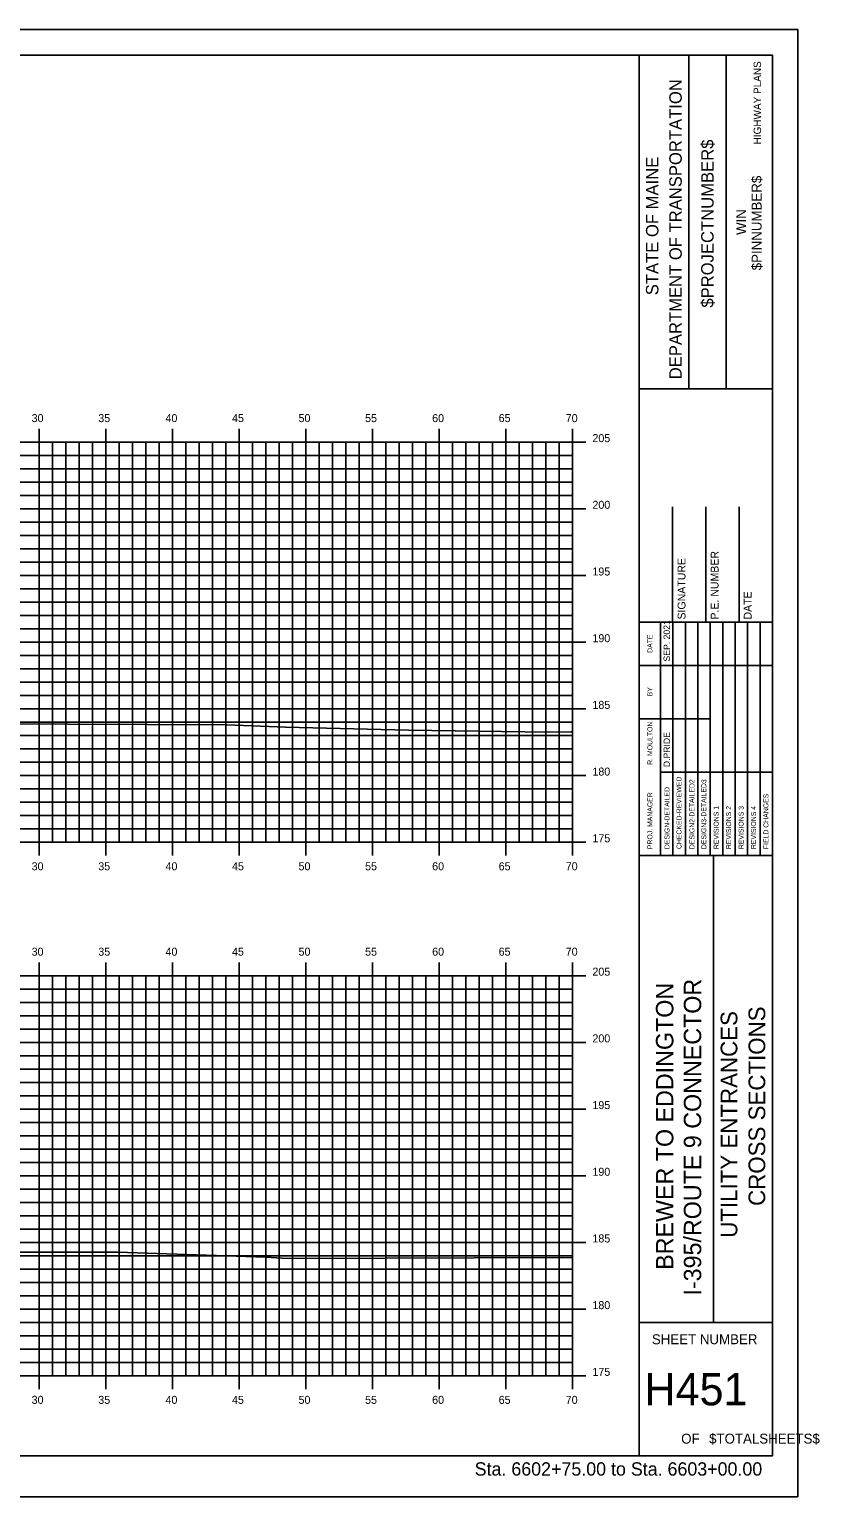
# Model space of a CAD drawing. Extents: x 1724405 to 1724577, y 459560 to 459670.
# Drawn here: x 1724517.3 to 1724576.5, y 459559.6 to 459669.6 of the extents above; entities that cross this region are included whole.
import ezdxf

# ---------------------------------------------------------------- set-up
doc = ezdxf.new("R2010")
doc.units = 0
for name, color, linetype in [('BORDER', 7, 'Continuous'), ('H_V ANNOTATION', 7, 'Continuous'), ('HIGHWAY_TITLE', 7, 'Continuous'), ('MAJOR', 7, 'Continuous'), ('MINOR', 7, 'Continuous'), ('PLOT BOUNDARY', 7, 'Continuous'), ('S_Roadway_Centerline', 7, 'Continuous')]:
    doc.layers.add(name, color=color, linetype=linetype)

msp = doc.modelspace()

# ---------------------------------------------------------------- linework, layer by layer
at = {"layer": 'BORDER'}
for p, q in [((1724562.99, 459562.61), (1724562.99, 459667.61)), ((1724566.71, 459642.61), (1724566.71, 459667.61)), ((1724569.51, 459642.61), (1724569.51, 459667.61)), ((1724562.99, 459642.61), (1724572.99, 459642.61)), ((1724565.49, 459625.12), (1724565.49, 459633.76)), ((1724567.99, 459625.12), (1724567.99, 459633.76)), ((1724570.49, 459625.12), (1724570.49, 459633.76)), ((1724562.99, 459625.12), (1724572.99, 459625.12)), ((1724562.99, 459607.62), (1724572.99, 459607.62)), ((1724568.58, 459572.62), (1724568.58, 459607.62)), ((1724562.99, 459572.62), (1724572.99, 459572.62))]:
    msp.add_line(p, q, dxfattribs=at)
msp.add_lwpolyline([(1724412.99, 459562.61), (1724572.99, 459562.61), (1724572.99, 459667.61), (1724412.99, 459667.61)], close=True, dxfattribs=at)
for points in [[(1724564.6, 459621.87), (1724564.6, 459625.12)], [(1724565.53, 459607.62), (1724565.53, 459625.12)], [(1724566.47, 459625.12), (1724566.47, 459607.62)], [(1724567.4, 459607.62), (1724567.4, 459625.12)], [(1724568.33, 459607.62), (1724568.33, 459625.12)], [(1724569.26, 459607.62), (1724569.26, 459625.12)], [(1724570.19, 459607.62), (1724570.19, 459625.12)], [(1724571.12, 459607.62), (1724571.12, 459625.12)], [(1724572.06, 459607.62), (1724572.06, 459625.12)], [(1724564.6, 459607.62), (1724564.6, 459624.41)], [(1724562.99, 459621.87), (1724572.99, 459621.87)], [(1724562.99, 459617.87), (1724564.6, 459617.87)], [(1724564.6, 459617.87), (1724568.33, 459617.87)], [(1724564.6, 459613.87), (1724572.99, 459613.87)]]:
    msp.add_lwpolyline(points, dxfattribs=at)
at = {"layer": 'MAJOR'}
for p, q in [((1724517.99, 459639.61), (1724517.99, 459638.61)), ((1724522.99, 459639.61), (1724522.99, 459638.61)), ((1724527.99, 459639.61), (1724527.99, 459638.61)), ((1724532.99, 459639.61), (1724532.99, 459638.61)), ((1724537.99, 459639.61), (1724537.99, 459638.61)), ((1724542.99, 459639.61), (1724542.99, 459638.61)), ((1724547.99, 459639.61), (1724547.99, 459638.61)), ((1724552.99, 459639.61), (1724552.99, 459638.61)), ((1724557.99, 459639.61), (1724557.99, 459638.61)), ((1724417.99, 459638.61), (1724557.99, 459638.61)), ((1724417.99, 459638.61), (1724557.99, 459638.61)), ((1724517.99, 459608.61), (1724517.99, 459638.61)), ((1724522.99, 459608.61), (1724522.99, 459638.61)), ((1724527.99, 459608.61), (1724527.99, 459638.61)), ((1724532.99, 459608.61), (1724532.99, 459638.61)), ((1724537.99, 459608.61), (1724537.99, 459638.61)), ((1724542.99, 459608.61), (1724542.99, 459638.61)), ((1724547.99, 459608.61), (1724547.99, 459638.61)), ((1724552.99, 459608.61), (1724552.99, 459638.61)), ((1724558.99, 459638.61), (1724556.98, 459638.61)), ((1724557.99, 459608.61), (1724557.99, 459638.61)), ((1724557.99, 459608.61), (1724557.99, 459638.61)), ((1724417.99, 459633.61), (1724557.99, 459633.61)), ((1724558.99, 459633.61), (1724556.98, 459633.61)), ((1724417.99, 459628.61), (1724557.99, 459628.61)), ((1724558.99, 459628.61), (1724556.98, 459628.61)), ((1724417.99, 459623.61), (1724557.99, 459623.61)), ((1724558.99, 459623.61), (1724556.98, 459623.61)), ((1724417.99, 459618.61), (1724557.99, 459618.61)), ((1724558.99, 459618.61), (1724556.98, 459618.61)), ((1724417.99, 459613.61), (1724557.99, 459613.61)), ((1724558.99, 459613.61), (1724556.98, 459613.61)), ((1724417.99, 459608.61), (1724557.99, 459608.61)), ((1724417.99, 459608.61), (1724557.99, 459608.61)), ((1724517.99, 459607.61), (1724517.99, 459608.61)), ((1724522.99, 459607.61), (1724522.99, 459608.61)), ((1724527.99, 459607.61), (1724527.99, 459608.61)), ((1724532.99, 459607.61), (1724532.99, 459608.61)), ((1724537.99, 459607.61), (1724537.99, 459608.61)), ((1724542.99, 459607.61), (1724542.99, 459608.61)), ((1724547.99, 459607.61), (1724547.99, 459608.61)), ((1724552.99, 459607.61), (1724552.99, 459608.61)), ((1724558.99, 459608.61), (1724556.98, 459608.61)), ((1724557.99, 459607.61), (1724557.99, 459608.61)), ((1724517.99, 459599.61), (1724517.99, 459598.61)), ((1724522.99, 459599.61), (1724522.99, 459598.61)), ((1724527.99, 459599.61), (1724527.99, 459598.61)), ((1724532.99, 459599.61), (1724532.99, 459598.61)), ((1724537.99, 459599.61), (1724537.99, 459598.61)), ((1724542.99, 459599.61), (1724542.99, 459598.61)), ((1724547.99, 459599.61), (1724547.99, 459598.61)), ((1724552.99, 459599.61), (1724552.99, 459598.61)), ((1724557.99, 459599.61), (1724557.99, 459598.61)), ((1724417.99, 459598.61), (1724557.99, 459598.61)), ((1724417.99, 459598.61), (1724557.99, 459598.61)), ((1724517.99, 459568.61), (1724517.99, 459598.61)), ((1724522.99, 459568.61), (1724522.99, 459598.61)), ((1724527.99, 459568.61), (1724527.99, 459598.61)), ((1724532.99, 459568.61), (1724532.99, 459598.61)), ((1724537.99, 459568.61), (1724537.99, 459598.61)), ((1724542.99, 459568.61), (1724542.99, 459598.61)), ((1724547.99, 459568.61), (1724547.99, 459598.61)), ((1724552.99, 459568.61), (1724552.99, 459598.61)), ((1724558.99, 459598.61), (1724556.98, 459598.61)), ((1724557.99, 459568.61), (1724557.99, 459598.61)), ((1724557.99, 459568.61), (1724557.99, 459598.61)), ((1724417.99, 459593.61), (1724557.99, 459593.61)), ((1724558.99, 459593.61), (1724556.98, 459593.61)), ((1724417.99, 459588.61), (1724557.99, 459588.61)), ((1724558.99, 459588.61), (1724556.98, 459588.61)), ((1724417.99, 459583.61), (1724557.99, 459583.61)), ((1724558.99, 459583.61), (1724556.98, 459583.61)), ((1724417.99, 459578.61), (1724557.99, 459578.61)), ((1724558.99, 459578.61), (1724556.98, 459578.61)), ((1724417.99, 459573.61), (1724557.99, 459573.61)), ((1724558.99, 459573.61), (1724556.98, 459573.61)), ((1724417.99, 459568.61), (1724557.99, 459568.61)), ((1724417.99, 459568.61), (1724557.99, 459568.61)), ((1724517.99, 459567.61), (1724517.99, 459568.61)), ((1724522.99, 459567.61), (1724522.99, 459568.61)), ((1724527.99, 459567.61), (1724527.99, 459568.61)), ((1724532.99, 459567.61), (1724532.99, 459568.61)), ((1724537.99, 459567.61), (1724537.99, 459568.61)), ((1724542.99, 459567.61), (1724542.99, 459568.61)), ((1724547.99, 459567.61), (1724547.99, 459568.61)), ((1724552.99, 459567.61), (1724552.99, 459568.61)), ((1724558.99, 459568.61), (1724556.98, 459568.61)), ((1724557.99, 459567.61), (1724557.99, 459568.61))]:
    msp.add_line(p, q, dxfattribs=at)
at = {"layer": 'MINOR'}
for p, q in [((1724518.99, 459608.61), (1724518.99, 459638.61)), ((1724519.99, 459608.61), (1724519.99, 459638.61)), ((1724520.99, 459608.61), (1724520.99, 459638.61)), ((1724521.99, 459608.61), (1724521.99, 459638.61)), ((1724523.99, 459608.61), (1724523.99, 459638.61)), ((1724524.99, 459608.61), (1724524.99, 459638.61)), ((1724525.99, 459608.61), (1724525.99, 459638.61)), ((1724526.99, 459608.61), (1724526.99, 459638.61)), ((1724528.99, 459608.61), (1724528.99, 459638.61)), ((1724529.99, 459608.61), (1724529.99, 459638.61)), ((1724530.99, 459608.61), (1724530.99, 459638.61)), ((1724531.99, 459608.61), (1724531.99, 459638.61)), ((1724533.99, 459608.61), (1724533.99, 459638.61)), ((1724534.99, 459608.61), (1724534.99, 459638.61)), ((1724535.99, 459608.61), (1724535.99, 459638.61)), ((1724536.99, 459608.61), (1724536.99, 459638.61)), ((1724538.99, 459608.61), (1724538.99, 459638.61)), ((1724539.99, 459608.61), (1724539.99, 459638.61)), ((1724540.99, 459608.61), (1724540.99, 459638.61)), ((1724541.99, 459608.61), (1724541.99, 459638.61)), ((1724543.99, 459608.61), (1724543.99, 459638.61)), ((1724544.99, 459608.61), (1724544.99, 459638.61)), ((1724545.99, 459608.61), (1724545.99, 459638.61)), ((1724546.99, 459608.61), (1724546.99, 459638.61)), ((1724548.99, 459608.61), (1724548.99, 459638.61)), ((1724549.99, 459608.61), (1724549.99, 459638.61)), ((1724550.99, 459608.61), (1724550.99, 459638.61)), ((1724551.99, 459608.61), (1724551.99, 459638.61)), ((1724553.99, 459608.61), (1724553.99, 459638.61)), ((1724554.99, 459608.61), (1724554.99, 459638.61)), ((1724555.99, 459608.61), (1724555.99, 459638.61)), ((1724556.99, 459608.61), (1724556.99, 459638.61)), ((1724417.99, 459637.61), (1724557.99, 459637.61)), ((1724557.99, 459637.61), (1724556.98, 459637.61)), ((1724417.99, 459636.61), (1724557.99, 459636.61)), ((1724557.99, 459636.61), (1724556.98, 459636.61)), ((1724417.99, 459635.61), (1724557.99, 459635.61)), ((1724557.99, 459635.61), (1724556.98, 459635.61)), ((1724417.99, 459634.61), (1724557.99, 459634.61)), ((1724557.99, 459634.61), (1724556.98, 459634.61)), ((1724417.99, 459632.61), (1724557.99, 459632.61)), ((1724557.99, 459632.61), (1724556.98, 459632.61)), ((1724417.99, 459631.61), (1724557.99, 459631.61)), ((1724417.99, 459630.61), (1724557.99, 459630.61)), ((1724557.99, 459631.61), (1724556.98, 459631.61)), ((1724557.99, 459630.61), (1724556.98, 459630.61)), ((1724417.99, 459629.61), (1724557.99, 459629.61)), ((1724557.99, 459629.61), (1724556.98, 459629.61)), ((1724417.99, 459627.61), (1724557.99, 459627.61)), ((1724557.99, 459627.61), (1724556.98, 459627.61)), ((1724417.99, 459626.61), (1724557.99, 459626.61)), ((1724557.99, 459626.61), (1724556.98, 459626.61)), ((1724417.99, 459625.61), (1724557.99, 459625.61)), ((1724557.99, 459625.61), (1724556.98, 459625.61)), ((1724417.99, 459624.61), (1724557.99, 459624.61)), ((1724557.99, 459624.61), (1724556.98, 459624.61)), ((1724417.99, 459622.61), (1724557.99, 459622.61)), ((1724557.99, 459622.61), (1724556.98, 459622.61)), ((1724417.99, 459621.61), (1724557.99, 459621.61)), ((1724557.99, 459621.61), (1724556.98, 459621.61)), ((1724417.99, 459620.61), (1724557.99, 459620.61)), ((1724417.99, 459619.61), (1724557.99, 459619.61)), ((1724557.99, 459620.61), (1724556.98, 459620.61)), ((1724557.99, 459619.61), (1724556.98, 459619.61)), ((1724417.99, 459617.61), (1724557.99, 459617.61)), ((1724557.99, 459617.61), (1724556.98, 459617.61)), ((1724417.99, 459616.61), (1724557.99, 459616.61)), ((1724557.99, 459616.61), (1724556.98, 459616.61)), ((1724417.99, 459615.61), (1724557.99, 459615.61)), ((1724557.99, 459615.61), (1724556.98, 459615.61)), ((1724417.99, 459614.61), (1724557.99, 459614.61)), ((1724557.99, 459614.61), (1724556.98, 459614.61)), ((1724417.99, 459612.61), (1724557.99, 459612.61)), ((1724557.99, 459612.61), (1724556.98, 459612.61)), ((1724417.99, 459611.61), (1724557.99, 459611.61)), ((1724557.99, 459611.61), (1724556.98, 459611.61)), ((1724417.99, 459610.61), (1724557.99, 459610.61)), ((1724557.99, 459610.61), (1724556.98, 459610.61)), ((1724417.99, 459609.61), (1724557.99, 459609.61)), ((1724557.99, 459609.61), (1724556.98, 459609.61)), ((1724417.99, 459597.61), (1724557.99, 459597.61)), ((1724518.99, 459568.61), (1724518.99, 459598.61)), ((1724519.99, 459568.61), (1724519.99, 459598.61)), ((1724520.99, 459568.61), (1724520.99, 459598.61)), ((1724521.99, 459568.61), (1724521.99, 459598.61)), ((1724523.99, 459568.61), (1724523.99, 459598.61)), ((1724524.99, 459568.61), (1724524.99, 459598.61)), ((1724525.99, 459568.61), (1724525.99, 459598.61)), ((1724526.99, 459568.61), (1724526.99, 459598.61)), ((1724528.99, 459568.61), (1724528.99, 459598.61)), ((1724529.99, 459568.61), (1724529.99, 459598.61)), ((1724530.99, 459568.61), (1724530.99, 459598.61)), ((1724531.99, 459568.61), (1724531.99, 459598.61)), ((1724533.99, 459568.61), (1724533.99, 459598.61)), ((1724534.99, 459568.61), (1724534.99, 459598.61)), ((1724535.99, 459568.61), (1724535.99, 459598.61)), ((1724536.99, 459568.61), (1724536.99, 459598.61)), ((1724538.99, 459568.61), (1724538.99, 459598.61)), ((1724539.99, 459568.61), (1724539.99, 459598.61)), ((1724540.99, 459568.61), (1724540.99, 459598.61)), ((1724541.99, 459568.61), (1724541.99, 459598.61)), ((1724543.99, 459568.61), (1724543.99, 459598.61)), ((1724544.99, 459568.61), (1724544.99, 459598.61)), ((1724545.99, 459568.61), (1724545.99, 459598.61)), ((1724546.99, 459568.61), (1724546.99, 459598.61)), ((1724548.99, 459568.61), (1724548.99, 459598.61)), ((1724549.99, 459568.61), (1724549.99, 459598.61)), ((1724550.99, 459568.61), (1724550.99, 459598.61)), ((1724551.99, 459568.61), (1724551.99, 459598.61)), ((1724553.99, 459568.61), (1724553.99, 459598.61)), ((1724554.99, 459568.61), (1724554.99, 459598.61)), ((1724555.99, 459568.61), (1724555.99, 459598.61)), ((1724557.99, 459597.61), (1724556.98, 459597.61)), ((1724556.99, 459568.61), (1724556.99, 459598.61)), ((1724417.99, 459596.61), (1724557.99, 459596.61)), ((1724557.99, 459596.61), (1724556.98, 459596.61)), ((1724417.99, 459595.61), (1724557.99, 459595.61)), ((1724557.99, 459595.61), (1724556.98, 459595.61)), ((1724417.99, 459594.61), (1724557.99, 459594.61)), ((1724557.99, 459594.61), (1724556.98, 459594.61)), ((1724417.99, 459592.61), (1724557.99, 459592.61)), ((1724557.99, 459592.61), (1724556.98, 459592.61)), ((1724417.99, 459591.61), (1724557.99, 459591.61)), ((1724557.99, 459591.61), (1724556.98, 459591.61)), ((1724417.99, 459590.61), (1724557.99, 459590.61)), ((1724557.99, 459590.61), (1724556.98, 459590.61)), ((1724417.99, 459589.61), (1724557.99, 459589.61)), ((1724557.99, 459589.61), (1724556.98, 459589.61)), ((1724417.99, 459587.61), (1724557.99, 459587.61)), ((1724417.99, 459586.61), (1724557.99, 459586.61)), ((1724557.99, 459587.61), (1724556.98, 459587.61)), ((1724557.99, 459586.61), (1724556.98, 459586.61)), ((1724417.99, 459585.61), (1724557.99, 459585.61)), ((1724557.99, 459585.61), (1724556.98, 459585.61)), ((1724417.99, 459584.61), (1724557.99, 459584.61)), ((1724557.99, 459584.61), (1724556.98, 459584.61)), ((1724417.99, 459582.61), (1724557.99, 459582.61)), ((1724557.99, 459582.61), (1724556.98, 459582.61)), ((1724417.99, 459581.61), (1724557.99, 459581.61)), ((1724557.99, 459581.61), (1724556.98, 459581.61)), ((1724417.99, 459580.61), (1724557.99, 459580.61)), ((1724557.99, 459580.61), (1724556.98, 459580.61)), ((1724417.99, 459579.61), (1724557.99, 459579.61)), ((1724557.99, 459579.61), (1724556.98, 459579.61)), ((1724417.99, 459577.61), (1724557.99, 459577.61)), ((1724557.99, 459577.61), (1724556.98, 459577.61)), ((1724417.99, 459576.61), (1724557.99, 459576.61)), ((1724417.99, 459575.61), (1724557.99, 459575.61)), ((1724557.99, 459576.61), (1724556.98, 459576.61)), ((1724557.99, 459575.61), (1724556.98, 459575.61)), ((1724417.99, 459574.61), (1724557.99, 459574.61)), ((1724557.99, 459574.61), (1724556.98, 459574.61)), ((1724417.99, 459572.61), (1724557.99, 459572.61)), ((1724557.99, 459572.61), (1724556.98, 459572.61)), ((1724417.99, 459571.61), (1724557.99, 459571.61)), ((1724557.99, 459571.61), (1724556.98, 459571.61)), ((1724417.99, 459570.61), (1724557.99, 459570.61)), ((1724557.99, 459570.61), (1724556.98, 459570.61)), ((1724417.99, 459569.61), (1724557.99, 459569.61)), ((1724557.99, 459569.61), (1724556.98, 459569.61))]:
    msp.add_line(p, q, dxfattribs=at)
at = {"layer": 'PLOT BOUNDARY'}
msp.add_lwpolyline([(1724404.89, 459559.55), (1724574.89, 459559.55), (1724574.89, 459669.55), (1724404.89, 459669.55)], close=True, dxfattribs=at)
at = {"layer": 'S_Roadway_Centerline'}
for points in [[(1724417.99, 459619.85), (1724418.89, 459619.83), (1724425.54, 459619.37), (1724434.97, 459618.78), (1724446.53, 459618.53), (1724460.12, 459618.37), (1724464.54, 459618.49), (1724469.23, 459618.37), (1724479.23, 459618.15), (1724484.8, 459618.1), (1724499.75, 459617.73), (1724508.71, 459617.44), (1724514.19, 459617.49), (1724532.07, 459617.41), (1724536.47, 459617.24), (1724545.7, 459617.02), (1724556.18, 459616.87), (1724557.88, 459616.89), (1724557.99, 459616.9)], [(1724417.99, 459580.32), (1724432.57, 459579.8), (1724439.05, 459579.67), (1724449.05, 459579.44), (1724463.39, 459578.96), (1724466.45, 459578.94), (1724487.3, 459577.78), (1724488.65, 459577.75), (1724491.14, 459577.74), (1724501.67, 459577.9), (1724512.87, 459577.9), (1724513.35, 459577.88), (1724523.87, 459577.87), (1724535, 459577.5), (1724536.23, 459577.43), (1724537.43, 459577.4), (1724557.22, 459577.48), (1724557.99, 459577.46)]]:
    msp.add_lwpolyline(points, dxfattribs=at)

# ---------------------------------------------------------------- texts
at = {"layer": 'BORDER'}
for s, height, p in [('DEPARTMENT OF TRANSPORTATION', 0.9318, (1724566.19, 459643.32)), ('$PROJECTNUMBER$', 0.9318, (1724568.58, 459648.69)), ('STATE OF MAINE', 0.9318, (1724564.44, 459649.62)), ('$PINNUMBER$', 0.7453, (1724572.18, 459651.49)), ('WIN', 0.745, (1724571.02, 459654.14)), ('SIGNATURE', 0.591, (1724566.47, 459625.31)), ('P.E. NUMBER', 0.5906, (1724568.95, 459625.31)), ('DATE', 0.591, (1724571.43, 459625.31)), ('SEP. 2021', 0.485, (1724565.31, 459622.16)), ('DATE', 0.371, (1724563.99, 459622.82)), ('BY', 0.371, (1724563.99, 459619.55)), ('R. MOULTON', 0.373, (1724563.99, 459614.42)), ('D.PRIDE', 0.485, (1724565.31, 459614.24)), ('CHECKED-REVIEWED', 0.3727, (1724566.17, 459608.1)), ('DESIGN2-DETAILED2', 0.3727, (1724567.14, 459608.1)), ('DESIGN3-DETAILED3', 0.3727, (1724568.03, 459608.1)), ('PROJ. MANAGER', 0.3727, (1724563.99, 459608.1)), ('DESIGN-DETAILED', 0.3727, (1724565.27, 459608.1)), ('FIELD CHANGES', 0.3727, (1724572.69, 459608.1)), ('REVISIONS 1', 0.3727, (1724568.96, 459608.1)), ('REVISIONS 2', 0.3727, (1724569.89, 459608.1)), ('REVISIONS 3', 0.3727, (1724570.83, 459608.1)), ('REVISIONS 4', 0.3727, (1724571.76, 459608.1)), ('UTILITY ENTRANCES', 1.25, (1724570.36, 459578.96)), ('CROSS SECTIONS', 1.25, (1724572.45, 459581.35))]:
    msp.add_text(s, height=height, rotation=90, dxfattribs=at).set_placement(p)
for s, height, p in [('SHEET NUMBER', 0.7453, (1724563.95, 459570.98)), ('H451', 2.419, (1724563.39, 459566.4)), ('OF', 0.745, (1724566.15, 459563.53)), ('$TOTALSHEETS$', 0.7453, (1724568.24, 459563.53))]:
    msp.add_text(s, height=height, dxfattribs=at).set_placement(p)
at = {"layer": 'H_V ANNOTATION'}
for s, height, p in [('30', 0.6, (1724517.43, 459640.11)), ('35', 0.6, (1724522.43, 459640.11)), ('40', 0.6, (1724527.47, 459640.11)), ('45', 0.6, (1724532.46, 459640.11)), ('50', 0.6, (1724537.45, 459640.11)), ('55', 0.6, (1724542.44, 459640.11)), ('60', 0.6, (1724547.47, 459640.11)), ('65', 0.6, (1724552.46, 459640.11)), ('70', 0.6, (1724557.49, 459640.11)), ('205', 0.6, (1724559.49, 459638.61)), ('200', 0.6, (1724559.49, 459633.61)), ('195', 0.6, (1724559.49, 459628.61)), ('190', 0.6, (1724559.49, 459623.61)), ('185', 0.6, (1724559.49, 459618.61)), ('180', 0.6, (1724559.49, 459613.61)), ('175', 0.6, (1724559.49, 459608.61)), ('30', 0.6, (1724517.43, 459606.51)), ('35', 0.6, (1724522.43, 459606.51)), ('40', 0.6, (1724527.47, 459606.51)), ('45', 0.6, (1724532.46, 459606.51)), ('50', 0.6, (1724537.45, 459606.51)), ('55', 0.6, (1724542.44, 459606.51)), ('60', 0.6, (1724547.47, 459606.51)), ('65', 0.6, (1724552.46, 459606.51)), ('70', 0.6, (1724557.49, 459606.51)), ('30', 0.6, (1724517.43, 459600.11)), ('35', 0.6, (1724522.43, 459600.11)), ('40', 0.6, (1724527.47, 459600.11)), ('45', 0.6, (1724532.46, 459600.11)), ('50', 0.6, (1724537.45, 459600.11)), ('55', 0.6, (1724542.44, 459600.11)), ('60', 0.6, (1724547.47, 459600.11)), ('65', 0.6, (1724552.46, 459600.11)), ('70', 0.6, (1724557.49, 459600.11)), ('205', 0.6, (1724559.49, 459598.61)), ('200', 0.6, (1724559.49, 459593.61)), ('195', 0.6, (1724559.49, 459588.61)), ('190', 0.6, (1724559.49, 459583.61)), ('185', 0.6, (1724559.49, 459578.61)), ('180', 0.6, (1724559.49, 459573.61)), ('175', 0.6, (1724559.49, 459568.61)), ('30', 0.6, (1724517.43, 459566.51)), ('35', 0.6, (1724522.43, 459566.51)), ('40', 0.6, (1724527.47, 459566.51)), ('45', 0.6, (1724532.46, 459566.51)), ('50', 0.6, (1724537.45, 459566.51)), ('55', 0.6, (1724542.44, 459566.51)), ('60', 0.6, (1724547.47, 459566.51)), ('65', 0.6, (1724552.46, 459566.51)), ('70', 0.6, (1724557.49, 459566.51)), ('Sta. 6602+75.00 to Sta. 6603+00.00', 1.0002, (1724550.66, 459561.13))]:
    msp.add_text(s, height=height, dxfattribs=at).set_placement(p)
at = {"layer": 'HIGHWAY_TITLE'}
for s, height, p in [('HIGHWAY PLANS', 0.559, (1724572.14, 459660.93)), ('BREWER TO EDDINGTON', 1.3043, (1724565.56, 459576.56)), ('I-395/ROUTE 9 CONNECTOR', 1.3043, (1724567.65, 459574.63))]:
    msp.add_text(s, height=height, rotation=90, dxfattribs=at).set_placement(p)

doc.saveas('drawing.dxf')
